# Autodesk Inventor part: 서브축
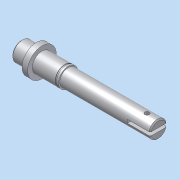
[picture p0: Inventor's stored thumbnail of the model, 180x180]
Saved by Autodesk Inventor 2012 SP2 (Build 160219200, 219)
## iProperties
Company: 한국ATC센터
Created: 2014-12
Part Number: 서브축
Document SubType Name: Modeling
Designer: KYOUNG IL JANG
Density: 1 g/cm^3
Mass: 23.2871 g
Surface Area: 76.512 cm^2
Volume: 23.2871 cm^3
Material: 기본값
Author: KYOUNG IL JANG
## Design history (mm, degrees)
sketch "스케치1"
  geometry: L1 (0, 0)-(120, 0); L2 (0, 0)-(0, 7.5); L3 (1, 8.5)-(13, 8.5); L4 (13, 8.5)-(13, 12.5); L5 (13, 12.5)-(18, 12.5); L6 (18, 12.5)-(18, 8.5); L7 (18, 8.5)-(41, 8.5); L8 (120, 7.5)-(120, 0); L9 (0, 7.5)-(1, 8.5); L10 (41, 8.5)-(41, 7.5); L11 (41, 7.5)-(120, 7.5); 1 further point
  constraints: 22 end point, 3 parallel, 3 perpendicular, 2 collinear, 2 point on line, 2 vertical, 1 horizontal
  dimensions: "d0" = 5 distance of L4.end L5.end; "d1" = 17 diameter of L7 L1; "d2" = 13 distance of point (0, 8.5) L3.end; "d3" = 25 diameter of L5 L1; "d4" = 120 distance of L1.start L1.end; "d5" = 1 distance of L2.end point (0, 8.5); "d6" = 1 distance of L3.start point (0, 8.5) (= d5); "d15" = 15 diameter of L11 L1; "d16" = 23 distance of L6.end L7.end
revolve "회전1" sketch "스케치1" stored, may be unused: angle "d9" = 90 deg
node "작업 평면1"
sketch "스케치2"
  geometry: L1 (11.5, 12.5)-(11.5, -12.5) reference; L2 (-3, 2.5)-(6, 2.5); L3 (6, -2.5)-(-3, -2.5); A1 r 2.5 centre (6, 0) between (6, -2.5) and (6, 2.5); A2 r 2.5 centre (-3, 0) between (-3, 2.5) and (-3, -2.5); 1 further point
  constraints: 4 end point, 4 point on circle, 4 tangent, 2 centre point, 1 horizontal alignment, 1 parallel, 1 perpendicular
  dimensions: "d10" = 5 distance between parallel lines of L3 L2; "d11" = 14 dimension on A1 A2; "d12" = 3 distance edge to line of A1 L1
extrude "돌출1" cut sketch "스케치2" distance "d13" = 3; taper "d14" = 0 deg
sketch "스케치3"
  geometry: L1 (18, -12.5)-(18, 12.5) reference; L2 (13, -12.5)-(13, 12.5) reference; L3 (18, 8.5)-(41, 8.5) reference; L4 (38, 8.5)-(39.15, 8.5); L5 (39.15, 8.5)-(39.15, 8.1); L6 (39.15, 8.1)-(38, 8.1); L7 (38, 8.1)-(38, 8.5); L8 (-24, 0)-(144, 0) reference; 1 further point
  constraints: 8 end point, 2 parallel, 1 horizontal, 1 perpendicular, 1 point on line
  dimensions: "d17" = 20 distance between parallel lines of L7 L1; "d18" = 1.15 distance of L5.end L6.end; "d19" = 8.1 distance between parallel lines of L6 L8
revolve "회전2" sketch "스케치3" stored, may be unused: angle "d20" = 90 deg
chamfer "모따기1" distance "d21" = 1; stored, may be unused: second distance "d22" = 2, angle "d23" = 45 deg
sketch "스케치4"
  geometry: L1 (-120, 1.5)-(-100, 1.5); L2 (-100, 1.5)-(-100, -1.5); L3 (-100, -1.5)-(-120, -1.5); L4 (-120, -1.5)-(-120, 1.5); L5 (-120, -6.5)-(-120, 6.5) reference; 2 further points
  constraints: 8 end point, 2 parallel, 1 collinear, 1 horizontal, 1 horizontal alignment, 1 midpoint, 1 perpendicular
  dimensions: "d24" = 3 distance between parallel lines of L3 L1; "d25" = 20 distance of L2.end L3.end
extrude "돌출2" cut sketch "스케치4" stored distance "d26" = 10; taper "d27" = 0 deg
sketch "스케치5"
  geometry: L1 (120, 6.325)-(120, -6.325) reference; C1 r 2 at (110, 0); 1 further point
  constraints: 1 centre point, 1 horizontal alignment
  dimensions: "d28" = 4 diameter of C1; "d29" = 10 distance from line of L1 C1.centre
extrude "돌출3" cut sketch "스케치5" stored distance "d30" = 10; taper "d31" = 0 deg
node "솔리드1"
node "투영된 루프1"
